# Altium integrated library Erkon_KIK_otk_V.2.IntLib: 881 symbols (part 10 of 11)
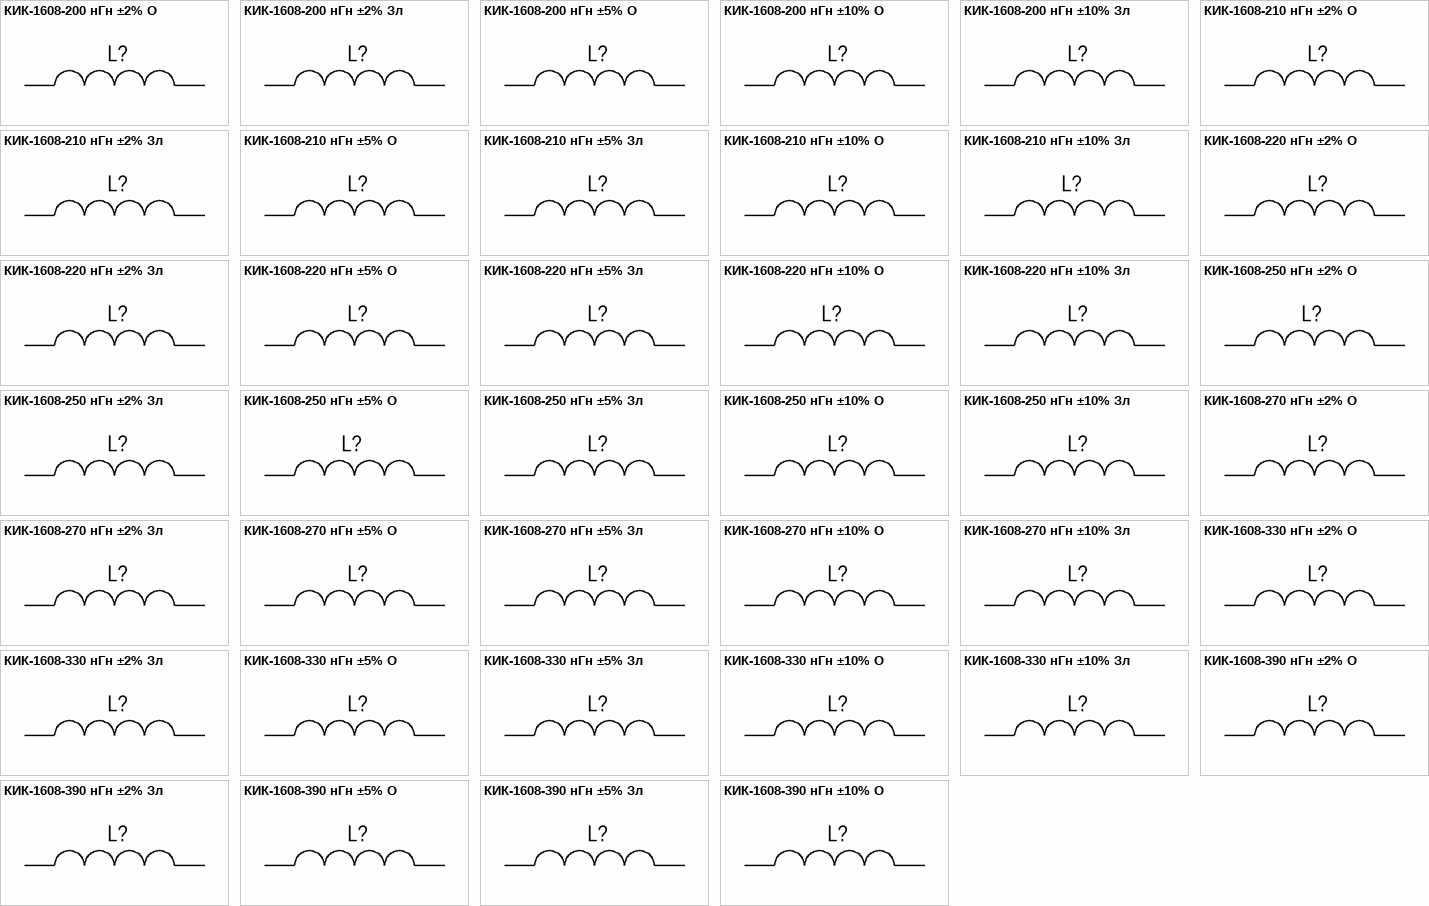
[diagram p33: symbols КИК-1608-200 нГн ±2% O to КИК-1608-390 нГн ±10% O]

## КИК-1608-250 нГн ±5% Зл
designator L?, comment 250 нГн ±5%  (value not drawn)
Катушка индуктивности с керамическим сердечником и золотым покрытием контактных площадок; Номиналиная индуктивность: 250 нГн; Добротность, не менее: 25; Резонансная частота, не менее: 0.822 ГГц; Сопротивление обмотки постоянноми току, не более: 3.55 Ом; Допустимый ток обмотки: 120 мА; Диапазон рабочих температур: от -60 до +125 ℃; Упаковка: Катушка и лента; Типоразмер: 1608 (0603); Технология монтажа: SMT; Изготовитель: АО "НПО "ЭРКОН"
footprint КИК-1608_Зл (Катушка индуктивности с керамическим сердечником  типоразмер 1005(0402))
pins: 1, 2

## КИК-1608-250 нГн ±10% O
designator L?, comment 250 нГн ±10%  (value not drawn)
Катушка индуктивности с керамическим сердечником и  финишным покрытием контактных площадок оловом; Номиналиная индуктивность: 250 нГн; Добротность, не менее: 25; Резонансная частота, не менее: 0.822 ГГц; Сопротивление обмотки постоянноми току, не более: 3.55 Ом; Допустимый ток обмотки: 120 мА; Диапазон рабочих температур: от -60 до +125 ℃; Упаковка: Катушка и лента; Типоразмер: 1608 (0603); Технология монтажа: SMT; Изготовитель: АО "НПО "ЭРКОН"
footprint КИК-1608_О (Катушка индуктивности с керамическим сердечником  типоразмер 1005(0402))
pins: 1, 2

## КИК-1608-250 нГн ±10% Зл
designator L?, comment 250 нГн ±10%  (value not drawn)
Катушка индуктивности с керамическим сердечником и золотым покрытием контактных площадок; Номиналиная индуктивность: 250 нГн; Добротность, не менее: 25; Резонансная частота, не менее: 0.822 ГГц; Сопротивление обмотки постоянноми току, не более: 3.55 Ом; Допустимый ток обмотки: 120 мА; Диапазон рабочих температур: от -60 до +125 ℃; Упаковка: Катушка и лента; Типоразмер: 1608 (0603); Технология монтажа: SMT; Изготовитель: АО "НПО "ЭРКОН"
footprint КИК-1608_Зл (Катушка индуктивности с керамическим сердечником  типоразмер 1005(0402))
pins: 1, 2

## КИК-1608-270 нГн ±2% O
designator L?, comment 270 нГн ±2%  (value not drawn)
Катушка индуктивности с керамическим сердечником и  финишным покрытием контактных площадок оловом; Номиналиная индуктивность: 270 нГн; Добротность, не менее: 25; Резонансная частота, не менее: 0.830 ГГц; Сопротивление обмотки постоянноми току, не более: 2.16 Ом; Допустимый ток обмотки: 170 мА; Диапазон рабочих температур: от -60 до +125 ℃; Упаковка: Катушка и лента; Типоразмер: 1608 (0603); Технология монтажа: SMT; Изготовитель: АО "НПО "ЭРКОН"
footprint КИК-1608_О (Катушка индуктивности с керамическим сердечником  типоразмер 1005(0402))
pins: 1, 2

## КИК-1608-270 нГн ±2% Зл
designator L?, comment 270 нГн ±2%  (value not drawn)
Катушка индуктивности с керамическим сердечником и золотым покрытием контактных площадок; Номиналиная индуктивность: 270 нГн; Добротность, не менее: 25; Резонансная частота, не менее: 0.830 ГГц; Сопротивление обмотки постоянноми току, не более: 2.16 Ом; Допустимый ток обмотки: 170 мА; Диапазон рабочих температур: от -60 до +125 ℃; Упаковка: Катушка и лента; Типоразмер: 1608 (0603); Технология монтажа: SMT; Изготовитель: АО "НПО "ЭРКОН"
footprint КИК-1608_Зл (Катушка индуктивности с керамическим сердечником  типоразмер 1005(0402))
pins: 1, 2

## КИК-1608-270 нГн ±5% O
designator L?, comment 270 нГн ±5%  (value not drawn)
Катушка индуктивности с керамическим сердечником и  финишным покрытием контактных площадок оловом; Номиналиная индуктивность: 270 нГн; Добротность, не менее: 25; Резонансная частота, не менее: 0.830 ГГц; Сопротивление обмотки постоянноми току, не более: 2.16 Ом; Допустимый ток обмотки: 170 мА; Диапазон рабочих температур: от -60 до +125 ℃; Упаковка: Катушка и лента; Типоразмер: 1608 (0603); Технология монтажа: SMT; Изготовитель: АО "НПО "ЭРКОН"
footprint КИК-1608_О (Катушка индуктивности с керамическим сердечником  типоразмер 1005(0402))
pins: 1, 2

## КИК-1608-270 нГн ±5% Зл
designator L?, comment 270 нГн ±5%  (value not drawn)
Катушка индуктивности с керамическим сердечником и золотым покрытием контактных площадок; Номиналиная индуктивность: 270 нГн; Добротность, не менее: 25; Резонансная частота, не менее: 0.830 ГГц; Сопротивление обмотки постоянноми току, не более: 2.16 Ом; Допустимый ток обмотки: 170 мА; Диапазон рабочих температур: от -60 до +125 ℃; Упаковка: Катушка и лента; Типоразмер: 1608 (0603); Технология монтажа: SMT; Изготовитель: АО "НПО "ЭРКОН"
footprint КИК-1608_Зл (Катушка индуктивности с керамическим сердечником  типоразмер 1005(0402))
pins: 1, 2

## КИК-1608-270 нГн ±10% O
designator L?, comment 270 нГн ±10%  (value not drawn)
Катушка индуктивности с керамическим сердечником и  финишным покрытием контактных площадок оловом; Номиналиная индуктивность: 270 нГн; Добротность, не менее: 25; Резонансная частота, не менее: 0.830 ГГц; Сопротивление обмотки постоянноми току, не более: 2.16 Ом; Допустимый ток обмотки: 170 мА; Диапазон рабочих температур: от -60 до +125 ℃; Упаковка: Катушка и лента; Типоразмер: 1608 (0603); Технология монтажа: SMT; Изготовитель: АО "НПО "ЭРКОН"
footprint КИК-1608_О (Катушка индуктивности с керамическим сердечником  типоразмер 1005(0402))
pins: 1, 2

## КИК-1608-270 нГн ±10% Зл
designator L?, comment 270 нГн ±10%  (value not drawn)
Катушка индуктивности с керамическим сердечником и золотым покрытием контактных площадок; Номиналиная индуктивность: 270 нГн; Добротность, не менее: 25; Резонансная частота, не менее: 0.830 ГГц; Сопротивление обмотки постоянноми току, не более: 2.16 Ом; Допустимый ток обмотки: 170 мА; Диапазон рабочих температур: от -60 до +125 ℃; Упаковка: Катушка и лента; Типоразмер: 1608 (0603); Технология монтажа: SMT; Изготовитель: АО "НПО "ЭРКОН"
footprint КИК-1608_Зл (Катушка индуктивности с керамическим сердечником  типоразмер 1005(0402))
pins: 1, 2

## КИК-1608-330 нГн ±2% O
designator L?, comment 330 нГн ±2%  (value not drawn)
Катушка индуктивности с керамическим сердечником и  финишным покрытием контактных площадок оловом; Номиналиная индуктивность: 330 нГн; Добротность, не менее: 25; Резонансная частота, не менее: 0.900 ГГц; Сопротивление обмотки постоянноми току, не более: 3.89 Ом; Допустимый ток обмотки: 100 мА; Диапазон рабочих температур: от -60 до +125 ℃; Упаковка: Катушка и лента; Типоразмер: 1608 (0603); Технология монтажа: SMT; Изготовитель: АО "НПО "ЭРКОН"
footprint КИК-1608_О (Катушка индуктивности с керамическим сердечником  типоразмер 1005(0402))
pins: 1, 2

## КИК-1608-330 нГн ±2% Зл
designator L?, comment 330 нГн ±2%  (value not drawn)
Катушка индуктивности с керамическим сердечником и золотым покрытием контактных площадок; Номиналиная индуктивность: 330 нГн; Добротность, не менее: 25; Резонансная частота, не менее: 0.900 ГГц; Сопротивление обмотки постоянноми току, не более: 3.89 Ом; Допустимый ток обмотки: 100 мА; Диапазон рабочих температур: от -60 до +125 ℃; Упаковка: Катушка и лента; Типоразмер: 1608 (0603); Технология монтажа: SMT; Изготовитель: АО "НПО "ЭРКОН"
footprint КИК-1608_Зл (Катушка индуктивности с керамическим сердечником  типоразмер 1005(0402))
pins: 1, 2

## КИК-1608-330 нГн ±5% O
designator L?, comment 330 нГн ±5%  (value not drawn)
Катушка индуктивности с керамическим сердечником и  финишным покрытием контактных площадок оловом; Номиналиная индуктивность: 330 нГн; Добротность, не менее: 25; Резонансная частота, не менее: 0.900 ГГц; Сопротивление обмотки постоянноми току, не более: 3.89 Ом; Допустимый ток обмотки: 100 мА; Диапазон рабочих температур: от -60 до +125 ℃; Упаковка: Катушка и лента; Типоразмер: 1608 (0603); Технология монтажа: SMT; Изготовитель: АО "НПО "ЭРКОН"
footprint КИК-1608_О (Катушка индуктивности с керамическим сердечником  типоразмер 1005(0402))
pins: 1, 2

## КИК-1608-330 нГн ±5% Зл
designator L?, comment 330 нГн ±5%  (value not drawn)
Катушка индуктивности с керамическим сердечником и золотым покрытием контактных площадок; Номиналиная индуктивность: 330 нГн; Добротность, не менее: 25; Резонансная частота, не менее: 0.900 ГГц; Сопротивление обмотки постоянноми току, не более: 3.89 Ом; Допустимый ток обмотки: 100 мА; Диапазон рабочих температур: от -60 до +125 ℃; Упаковка: Катушка и лента; Типоразмер: 1608 (0603); Технология монтажа: SMT; Изготовитель: АО "НПО "ЭРКОН"
footprint КИК-1608_Зл (Катушка индуктивности с керамическим сердечником  типоразмер 1005(0402))
pins: 1, 2

## КИК-1608-330 нГн ±10% O
designator L?, comment 330 нГн ±10%  (value not drawn)
Катушка индуктивности с керамическим сердечником и  финишным покрытием контактных площадок оловом; Номиналиная индуктивность: 330 нГн; Добротность, не менее: 25; Резонансная частота, не менее: 0.900 ГГц; Сопротивление обмотки постоянноми току, не более: 3.89 Ом; Допустимый ток обмотки: 100 мА; Диапазон рабочих температур: от -60 до +125 ℃; Упаковка: Катушка и лента; Типоразмер: 1608 (0603); Технология монтажа: SMT; Изготовитель: АО "НПО "ЭРКОН"
footprint КИК-1608_О (Катушка индуктивности с керамическим сердечником  типоразмер 1005(0402))
pins: 1, 2

## КИК-1608-330 нГн ±10% Зл
designator L?, comment 330 нГн ±10%  (value not drawn)
Катушка индуктивности с керамическим сердечником и золотым покрытием контактных площадок; Номиналиная индуктивность: 330 нГн; Добротность, не менее: 25; Резонансная частота, не менее: 0.900 ГГц; Сопротивление обмотки постоянноми току, не более: 3.89 Ом; Допустимый ток обмотки: 100 мА; Диапазон рабочих температур: от -60 до +125 ℃; Упаковка: Катушка и лента; Типоразмер: 1608 (0603); Технология монтажа: SMT; Изготовитель: АО "НПО "ЭРКОН"
footprint КИК-1608_Зл (Катушка индуктивности с керамическим сердечником  типоразмер 1005(0402))
pins: 1, 2

## КИК-1608-390 нГн ±2% O
designator L?, comment 390 нГн ±2%  (value not drawn)
Катушка индуктивности с керамическим сердечником и  финишным покрытием контактных площадок оловом; Номиналиная индуктивность: 390 нГн; Добротность, не менее: 25; Резонансная частота, не менее: 0.780 ГГц; Сопротивление обмотки постоянноми току, не более: 4.35 Ом; Допустимый ток обмотки: 100 мА; Диапазон рабочих температур: от -60 до +125 ℃; Упаковка: Катушка и лента; Типоразмер: 1608 (0603); Технология монтажа: SMT; Изготовитель: АО "НПО "ЭРКОН"
footprint КИК-1608_О (Катушка индуктивности с керамическим сердечником  типоразмер 1005(0402))
pins: 1, 2

## КИК-1608-390 нГн ±2% Зл
designator L?, comment 390 нГн ±2%  (value not drawn)
Катушка индуктивности с керамическим сердечником и золотым покрытием контактных площадок; Номиналиная индуктивность: 390 нГн; Добротность, не менее: 25; Резонансная частота, не менее: 0.780 ГГц; Сопротивление обмотки постоянноми току, не более: 4.35 Ом; Допустимый ток обмотки: 100 мА; Диапазон рабочих температур: от -60 до +125 ℃; Упаковка: Катушка и лента; Типоразмер: 1608 (0603); Технология монтажа: SMT; Изготовитель: АО "НПО "ЭРКОН"
footprint КИК-1608_Зл (Катушка индуктивности с керамическим сердечником  типоразмер 1005(0402))
pins: 1, 2

## КИК-1608-390 нГн ±5% O
designator L?, comment 390 нГн ±5%  (value not drawn)
Катушка индуктивности с керамическим сердечником и  финишным покрытием контактных площадок оловом; Номиналиная индуктивность: 390 нГн; Добротность, не менее: 25; Резонансная частота, не менее: 0.780 ГГц; Сопротивление обмотки постоянноми току, не более: 4.35 Ом; Допустимый ток обмотки: 100 мА; Диапазон рабочих температур: от -60 до +125 ℃; Упаковка: Катушка и лента; Типоразмер: 1608 (0603); Технология монтажа: SMT; Изготовитель: АО "НПО "ЭРКОН"
footprint КИК-1608_О (Катушка индуктивности с керамическим сердечником  типоразмер 1005(0402))
pins: 1, 2

## КИК-1608-390 нГн ±5% Зл
designator L?, comment 390 нГн ±5%  (value not drawn)
Катушка индуктивности с керамическим сердечником и золотым покрытием контактных площадок; Номиналиная индуктивность: 390 нГн; Добротность, не менее: 25; Резонансная частота, не менее: 0.780 ГГц; Сопротивление обмотки постоянноми току, не более: 4.35 Ом; Допустимый ток обмотки: 100 мА; Диапазон рабочих температур: от -60 до +125 ℃; Упаковка: Катушка и лента; Типоразмер: 1608 (0603); Технология монтажа: SMT; Изготовитель: АО "НПО "ЭРКОН"
footprint КИК-1608_Зл (Катушка индуктивности с керамическим сердечником  типоразмер 1005(0402))
pins: 1, 2

## КИК-1608-390 нГн ±10% O
designator L?, comment 390 нГн ±10%  (value not drawn)
Катушка индуктивности с керамическим сердечником и  финишным покрытием контактных площадок оловом; Номиналиная индуктивность: 390 нГн; Добротность, не менее: 25; Резонансная частота, не менее: 0.780 ГГц; Сопротивление обмотки постоянноми току, не более: 4.35 Ом; Допустимый ток обмотки: 100 мА; Диапазон рабочих температур: от -60 до +125 ℃; Упаковка: Катушка и лента; Типоразмер: 1608 (0603); Технология монтажа: SMT; Изготовитель: АО "НПО "ЭРКОН"
footprint КИК-1608_О (Катушка индуктивности с керамическим сердечником  типоразмер 1005(0402))
pins: 1, 2

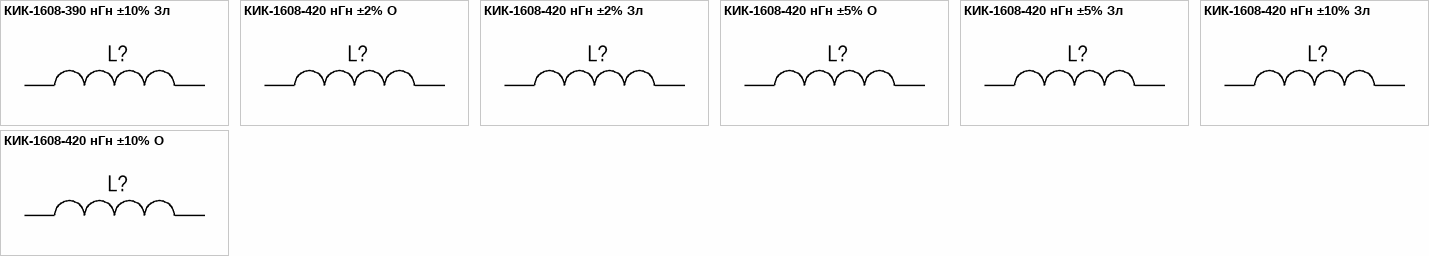
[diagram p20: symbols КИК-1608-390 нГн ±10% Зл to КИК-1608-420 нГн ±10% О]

## КИК-1608-390 нГн ±10% Зл
designator L?, comment 390 нГн ±10%  (value not drawn)
Катушка индуктивности с керамическим сердечником и золотым покрытием контактных площадок; Номиналиная индуктивность: 390 нГн; Добротность, не менее: 25; Резонансная частота, не менее: 0.780 ГГц; Сопротивление обмотки постоянноми току, не более: 4.35 Ом; Допустимый ток обмотки: 100 мА; Диапазон рабочих температур: от -60 до +125 ℃; Упаковка: Катушка и лента; Типоразмер: 1608 (0603); Технология монтажа: SMT; Изготовитель: АО "НПО "ЭРКОН"
footprint КИК-1608_Зл (Катушка индуктивности с керамическим сердечником  типоразмер 1005(0402))
pins: 1, 2

## КИК-1608-420 нГн ±2% O
designator L?, comment 420 нГн ±2%  (value not drawn)
Катушка индуктивности с керамическим сердечником и  финишным покрытием контактных площадок оловом; Номиналиная индуктивность: 420 нГн; Добротность, не менее: 20; Резонансная частота, не менее: 0.680 ГГц; Сопротивление обмотки постоянноми току, не более: 4.45 Ом; Допустимый ток обмотки: 100 мА; Диапазон рабочих температур: от -60 до +125 ℃; Упаковка: Катушка и лента; Типоразмер: 1608 (0603); Технология монтажа: SMT; Изготовитель: АО "НПО "ЭРКОН"
footprint КИК-1608_О (Катушка индуктивности с керамическим сердечником  типоразмер 1005(0402))
pins: 1, 2

## КИК-1608-420 нГн ±2% Зл
designator L?, comment 420 нГн ±2%  (value not drawn)
Катушка индуктивности с керамическим сердечником и золотым покрытием контактных площадок; Номиналиная индуктивность: 420 нГн; Добротность, не менее: 20; Резонансная частота, не менее: 0.680 ГГц; Сопротивление обмотки постоянноми току, не более: 4.45 Ом; Допустимый ток обмотки: 100 мА; Диапазон рабочих температур: от -60 до +125 ℃; Упаковка: Катушка и лента; Типоразмер: 1608 (0603); Технология монтажа: SMT; Изготовитель: АО "НПО "ЭРКОН"
footprint КИК-1608_Зл (Катушка индуктивности с керамическим сердечником  типоразмер 1005(0402))
pins: 1, 2

## КИК-1608-420 нГн ±5% O
designator L?, comment 420 нГн ±5%  (value not drawn)
Катушка индуктивности с керамическим сердечником и  финишным покрытием контактных площадок оловом; Номиналиная индуктивность: 420 нГн; Добротность, не менее: 20; Резонансная частота, не менее: 0.680 ГГц; Сопротивление обмотки постоянноми току, не более: 4.45 Ом; Допустимый ток обмотки: 100 мА; Диапазон рабочих температур: от -60 до +125 ℃; Упаковка: Катушка и лента; Типоразмер: 1608 (0603); Технология монтажа: SMT; Изготовитель: АО "НПО "ЭРКОН"
footprint КИК-1608_О (Катушка индуктивности с керамическим сердечником  типоразмер 1005(0402))
pins: 1, 2

## КИК-1608-420 нГн ±5% Зл
designator L?, comment 420 нГн ±5%  (value not drawn)
Катушка индуктивности с керамическим сердечником и золотым покрытием контактных площадок; Номиналиная индуктивность: 420 нГн; Добротность, не менее: 20; Резонансная частота, не менее: 0.680 ГГц; Сопротивление обмотки постоянноми току, не более: 4.45 Ом; Допустимый ток обмотки: 100 мА; Диапазон рабочих температур: от -60 до +125 ℃; Упаковка: Катушка и лента; Типоразмер: 1608 (0603); Технология монтажа: SMT; Изготовитель: АО "НПО "ЭРКОН"
footprint КИК-1608_Зл (Катушка индуктивности с керамическим сердечником  типоразмер 1005(0402))
pins: 1, 2

## КИК-1608-420 нГн ±10% Зл
designator L?, comment 420 нГн ±10%  (value not drawn)
Катушка индуктивности с керамическим сердечником и золотым покрытием контактных площадок; Номиналиная индуктивность: 420 нГн; Добротность, не менее: 20; Резонансная частота, не менее: 0.680 ГГц; Сопротивление обмотки постоянноми току, не более: 4.45 Ом; Допустимый ток обмотки: 100 мА; Диапазон рабочих температур: от -60 до +125 ℃; Упаковка: Катушка и лента; Типоразмер: 1608 (0603); Технология монтажа: SMT; Изготовитель: АО "НПО "ЭРКОН"
footprint КИК-1608_Зл (Катушка индуктивности с керамическим сердечником  типоразмер 1005(0402))
pins: 1, 2

## КИК-1608-420 нГн ±10% О
designator L?, comment 420 нГн ±10%  (value not drawn)
Катушка индуктивности с керамическим сердечником и  финишным покрытием контактных площадок оловом; Номиналиная индуктивность: 420 нГн; Добротность, не менее: 20; Резонансная частота, не менее: 0.680 ГГц; Сопротивление обмотки постоянноми току, не более: 4.45 Ом; Допустимый ток обмотки: 100 мА; Диапазон рабочих температур: от -60 до +125 ℃; Упаковка: Катушка и лента; Типоразмер: 1608 (0603); Технология монтажа: SMT; Изготовитель: АО "НПО "ЭРКОН"
footprint КИК-1608_О (Катушка индуктивности с керамическим сердечником  типоразмер 1005(0402))
pins: 1, 2


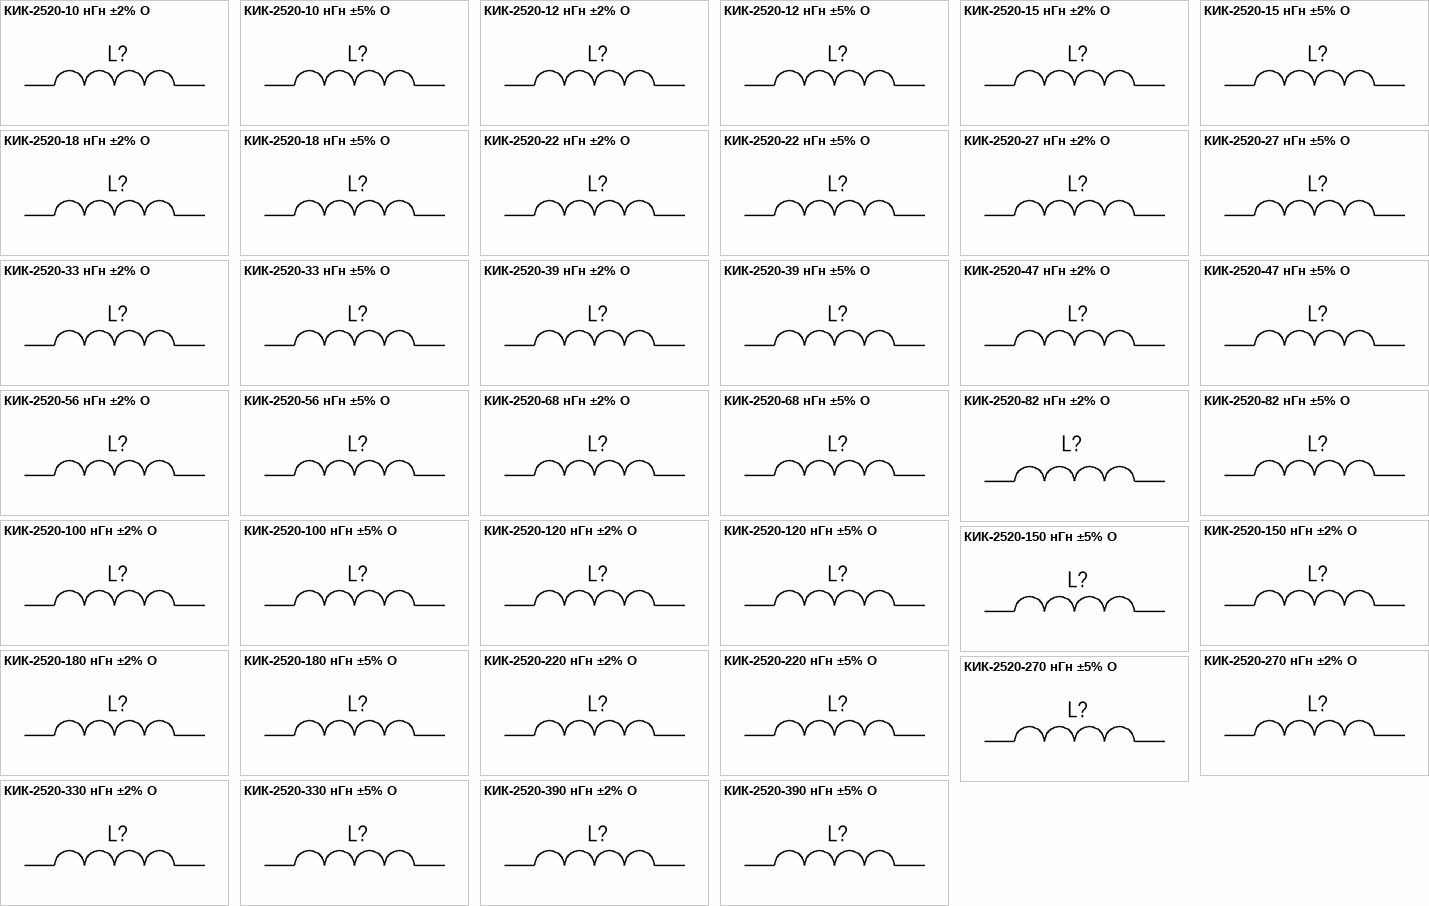
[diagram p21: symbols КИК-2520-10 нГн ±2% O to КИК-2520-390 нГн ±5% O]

## КИК-2520-10 нГн ±2% O
designator L?, comment 10 нГн ±2%  (value not drawn)
Катушка индуктивности с керамическим сердечником и  финишным покрытием контактных площадок оловом; Номиналиная индуктивность: 10 нГн; Добротность, не менее: 50; Резонансная частота, не менее: 4.10 ГГц; Сопротивление обмотки постоянноми току, не более: 0.08 Ом; Допустимый ток обмотки: 1000 мА; Диапазон рабочих температур: от -60 до +125 ℃; Упаковка: Катушка и лента; Типоразмер: 2520 (1008); Технология монтажа: SMT; Изготовитель: АО "НПО "ЭРКОН"
footprint КИК-2520-О (Катушка индуктивности с керамическим сердечником типоразмер 2520(1008))
pins: 1, 2

## КИК-2520-10 нГн ±5% O
designator L?, comment 10 нГн ±5%  (value not drawn)
Катушка индуктивности с керамическим сердечником и  финишным покрытием контактных площадок оловом; Номиналиная индуктивность: 10 нГн; Добротность, не менее: 50; Резонансная частота, не менее: 4.10 ГГц; Сопротивление обмотки постоянноми току, не более: 0.08 Ом; Допустимый ток обмотки: 1000 мА; Диапазон рабочих температур: от -60 до +125 ℃; Упаковка: Катушка и лента; Типоразмер: 2520 (1008); Технология монтажа: SMT; Изготовитель: АО "НПО "ЭРКОН"
footprint КИК-2520-О (Катушка индуктивности с керамическим сердечником типоразмер 2520(1008))
pins: 1, 2

## КИК-2520-12 нГн ±2% O
designator L?, comment 12 нГн ±2%  (value not drawn)
Катушка индуктивности с керамическим сердечником и  финишным покрытием контактных площадок оловом; Номиналиная индуктивность: 12 нГн; Добротность, не менее: 50; Резонансная частота, не менее: 3.30 ГГц; Сопротивление обмотки постоянноми току, не более: 0.09 Ом; Допустимый ток обмотки: 1000 мА; Диапазон рабочих температур: от -60 до +125 ℃; Упаковка: Катушка и лента; Типоразмер: 2520 (1008); Технология монтажа: SMT; Изготовитель: АО "НПО "ЭРКОН"
footprint КИК-2520-О (Катушка индуктивности с керамическим сердечником типоразмер 2520(1008))
pins: 1, 2

## КИК-2520-12 нГн ±5% O
designator L?, comment 12 нГн ±5%  (value not drawn)
Катушка индуктивности с керамическим сердечником и  финишным покрытием контактных площадок оловом; Номиналиная индуктивность: 12 нГн; Добротность, не менее: 50; Резонансная частота, не менее: 3.30 ГГц; Сопротивление обмотки постоянноми току, не более: 0.09 Ом; Допустимый ток обмотки: 1000 мА; Диапазон рабочих температур: от -60 до +125 ℃; Упаковка: Катушка и лента; Типоразмер: 2520 (1008); Технология монтажа: SMT; Изготовитель: АО "НПО "ЭРКОН"
footprint КИК-2520-О (Катушка индуктивности с керамическим сердечником типоразмер 2520(1008))
pins: 1, 2

## КИК-2520-15 нГн ±2% O
designator L?, comment 15 нГн ±2%  (value not drawn)
Катушка индуктивности с керамическим сердечником и  финишным покрытием контактных площадок оловом; Номиналиная индуктивность: 15 нГн; Добротность, не менее: 50; Резонансная частота, не менее: 2.50 ГГц; Сопротивление обмотки постоянноми току, не более: 0.10 Ом; Допустимый ток обмотки: 1000 мА; Диапазон рабочих температур: от -60 до +125 ℃; Упаковка: Катушка и лента; Типоразмер: 2520 (1008); Технология монтажа: SMT; Изготовитель: АО "НПО "ЭРКОН"
footprint КИК-2520-О (Катушка индуктивности с керамическим сердечником типоразмер 2520(1008))
pins: 1, 2

## КИК-2520-15 нГн ±5% O
designator L?, comment 15 нГн ±5%  (value not drawn)
Катушка индуктивности с керамическим сердечником и  финишным покрытием контактных площадок оловом; Номиналиная индуктивность: 15 нГн; Добротность, не менее: 50; Резонансная частота, не менее: 2.50 ГГц; Сопротивление обмотки постоянноми току, не более: 0.10 Ом; Допустимый ток обмотки: 1000 мА; Диапазон рабочих температур: от -60 до +125 ℃; Упаковка: Катушка и лента; Типоразмер: 2520 (1008); Технология монтажа: SMT; Изготовитель: АО "НПО "ЭРКОН"
footprint КИК-2520-О (Катушка индуктивности с керамическим сердечником типоразмер 2520(1008))
pins: 1, 2

## КИК-2520-18 нГн ±2% O
designator L?, comment 18 нГн ±2%  (value not drawn)
Катушка индуктивности с керамическим сердечником и  финишным покрытием контактных площадок оловом; Номиналиная индуктивность: 18 нГн; Добротность, не менее: 50; Резонансная частота, не менее: 2.50 ГГц; Сопротивление обмотки постоянноми току, не более: 0.11 Ом; Допустимый ток обмотки: 1000 мА; Диапазон рабочих температур: от -60 до +125 ℃; Упаковка: Катушка и лента; Типоразмер: 2520 (1008); Технология монтажа: SMT; Изготовитель: АО "НПО "ЭРКОН"
footprint КИК-2520-О (Катушка индуктивности с керамическим сердечником типоразмер 2520(1008))
pins: 1, 2

## КИК-2520-18 нГн ±5% O
designator L?, comment 18 нГн ±5%  (value not drawn)
Катушка индуктивности с керамическим сердечником и  финишным покрытием контактных площадок оловом; Номиналиная индуктивность: 18 нГн; Добротность, не менее: 50; Резонансная частота, не менее: 2.50 ГГц; Сопротивление обмотки постоянноми току, не более: 0.11 Ом; Допустимый ток обмотки: 1000 мА; Диапазон рабочих температур: от -60 до +125 ℃; Упаковка: Катушка и лента; Типоразмер: 2520 (1008); Технология монтажа: SMT; Изготовитель: АО "НПО "ЭРКОН"
footprint КИК-2520-О (Катушка индуктивности с керамическим сердечником типоразмер 2520(1008))
pins: 1, 2

## КИК-2520-22 нГн ±2% O
designator L?, comment 22 нГн ±2%  (value not drawn)
Катушка индуктивности с керамическим сердечником и  финишным покрытием контактных площадок оловом; Номиналиная индуктивность: 22 нГн; Добротность, не менее: 55; Резонансная частота, не менее: 2.40 ГГц; Сопротивление обмотки постоянноми току, не более: 0.12 Ом; Допустимый ток обмотки: 1000 мА; Диапазон рабочих температур: от -60 до +125 ℃; Упаковка: Катушка и лента; Типоразмер: 2520 (1008); Технология монтажа: SMT; Изготовитель: АО "НПО "ЭРКОН"
footprint КИК-2520-О (Катушка индуктивности с керамическим сердечником типоразмер 2520(1008))
pins: 1, 2

## КИК-2520-22 нГн ±5% O
designator L?, comment 22 нГн ±5%  (value not drawn)
Катушка индуктивности с керамическим сердечником и  финишным покрытием контактных площадок оловом; Номиналиная индуктивность: 22 нГн; Добротность, не менее: 55; Резонансная частота, не менее: 2.40 ГГц; Сопротивление обмотки постоянноми току, не более: 0.12 Ом; Допустимый ток обмотки: 1000 мА; Диапазон рабочих температур: от -60 до +125 ℃; Упаковка: Катушка и лента; Типоразмер: 2520 (1008); Технология монтажа: SMT; Изготовитель: АО "НПО "ЭРКОН"
footprint КИК-2520-О (Катушка индуктивности с керамическим сердечником типоразмер 2520(1008))
pins: 1, 2

## КИК-2520-27 нГн ±2% O
designator L?, comment 27 нГн ±2%  (value not drawn)
Катушка индуктивности с керамическим сердечником и  финишным покрытием контактных площадок оловом; Номиналиная индуктивность: 27 нГн; Добротность, не менее: 55; Резонансная частота, не менее: 1.60 ГГц; Сопротивление обмотки постоянноми току, не более: 0.13 Ом; Допустимый ток обмотки: 1000 мА; Диапазон рабочих температур: от -60 до +125 ℃; Упаковка: Катушка и лента; Типоразмер: 2520 (1008); Технология монтажа: SMT; Изготовитель: АО "НПО "ЭРКОН"
footprint КИК-2520-О (Катушка индуктивности с керамическим сердечником типоразмер 2520(1008))
pins: 1, 2

## КИК-2520-27 нГн ±5% O
designator L?, comment 27 нГн ±5%  (value not drawn)
Катушка индуктивности с керамическим сердечником и  финишным покрытием контактных площадок оловом; Номиналиная индуктивность: 27 нГн; Добротность, не менее: 55; Резонансная частота, не менее: 1.60 ГГц; Сопротивление обмотки постоянноми току, не более: 0.13 Ом; Допустимый ток обмотки: 1000 мА; Диапазон рабочих температур: от -60 до +125 ℃; Упаковка: Катушка и лента; Типоразмер: 2520 (1008); Технология монтажа: SMT; Изготовитель: АО "НПО "ЭРКОН"
footprint КИК-2520-О (Катушка индуктивности с керамическим сердечником типоразмер 2520(1008))
pins: 1, 2

## КИК-2520-33 нГн ±2% O
designator L?, comment 33 нГн ±2%  (value not drawn)
Катушка индуктивности с керамическим сердечником и  финишным покрытием контактных площадок оловом; Номиналиная индуктивность: 33 нГн; Добротность, не менее: 60; Резонансная частота, не менее: 1.60 ГГц; Сопротивление обмотки постоянноми току, не более: 0.14 Ом; Допустимый ток обмотки: 1000 мА; Диапазон рабочих температур: от -60 до +125 ℃; Упаковка: Катушка и лента; Типоразмер: 2520 (1008); Технология монтажа: SMT; Изготовитель: АО "НПО "ЭРКОН"
footprint КИК-2520-О (Катушка индуктивности с керамическим сердечником типоразмер 2520(1008))
pins: 1, 2

## КИК-2520-33 нГн ±5% O
designator L?, comment 33 нГн ±5%  (value not drawn)
Катушка индуктивности с керамическим сердечником и  финишным покрытием контактных площадок оловом; Номиналиная индуктивность: 33 нГн; Добротность, не менее: 60; Резонансная частота, не менее: 1.60 ГГц; Сопротивление обмотки постоянноми току, не более: 0.14 Ом; Допустимый ток обмотки: 1000 мА; Диапазон рабочих температур: от -60 до +125 ℃; Упаковка: Катушка и лента; Типоразмер: 2520 (1008); Технология монтажа: SMT; Изготовитель: АО "НПО "ЭРКОН"
footprint КИК-2520-О (Катушка индуктивности с керамическим сердечником типоразмер 2520(1008))
pins: 1, 2

## КИК-2520-39 нГн ±2% O
designator L?, comment 39 нГн ±2%  (value not drawn)
Катушка индуктивности с керамическим сердечником и  финишным покрытием контактных площадок оловом; Номиналиная индуктивность: 33 нГн; Добротность, не менее: 60; Резонансная частота, не менее: 1.50 ГГц; Сопротивление обмотки постоянноми току, не более: 0.15 Ом; Допустимый ток обмотки: 1000 мА; Диапазон рабочих температур: от -60 до +125 ℃; Упаковка: Катушка и лента; Типоразмер: 2520 (1008); Технология монтажа: SMT; Изготовитель: АО "НПО "ЭРКОН"
footprint КИК-2520-О (Катушка индуктивности с керамическим сердечником типоразмер 2520(1008))
pins: 1, 2

## КИК-2520-39 нГн ±5% O
designator L?, comment 39 нГн ±5%  (value not drawn)
Катушка индуктивности с керамическим сердечником и  финишным покрытием контактных площадок оловом; Номиналиная индуктивность: 33 нГн; Добротность, не менее: 60; Резонансная частота, не менее: 1.50 ГГц; Сопротивление обмотки постоянноми току, не более: 0.15 Ом; Допустимый ток обмотки: 1000 мА; Диапазон рабочих температур: от -60 до +125 ℃; Упаковка: Катушка и лента; Типоразмер: 2520 (1008); Технология монтажа: SMT; Изготовитель: АО "НПО "ЭРКОН"
footprint КИК-2520-О (Катушка индуктивности с керамическим сердечником типоразмер 2520(1008))
pins: 1, 2

## КИК-2520-47 нГн ±2% O
designator L?, comment 47 нГн ±2%  (value not drawn)
Катушка индуктивности с керамическим сердечником и  финишным покрытием контактных площадок оловом; Номиналиная индуктивность: 47 нГн; Добротность, не менее: 65; Резонансная частота, не менее: 1.50 ГГц; Сопротивление обмотки постоянноми току, не более: 0.16 Ом; Допустимый ток обмотки: 1000 мА; Диапазон рабочих температур: от -60 до +125 ℃; Упаковка: Катушка и лента; Типоразмер: 2520 (1008); Технология монтажа: SMT; Изготовитель: АО "НПО "ЭРКОН"
footprint КИК-2520-О (Катушка индуктивности с керамическим сердечником типоразмер 2520(1008))
pins: 1, 2

## КИК-2520-47 нГн ±5% O
designator L?, comment 47 нГн ±5%  (value not drawn)
Катушка индуктивности с керамическим сердечником и  финишным покрытием контактных площадок оловом; Номиналиная индуктивность: 47 нГн; Добротность, не менее: 65; Резонансная частота, не менее: 1.50 ГГц; Сопротивление обмотки постоянноми току, не более: 0.16 Ом; Допустимый ток обмотки: 1000 мА; Диапазон рабочих температур: от -60 до +125 ℃; Упаковка: Катушка и лента; Типоразмер: 2520 (1008); Технология монтажа: SMT; Изготовитель: АО "НПО "ЭРКОН"
footprint КИК-2520-О (Катушка индуктивности с керамическим сердечником типоразмер 2520(1008))
pins: 1, 2

## КИК-2520-56 нГн ±2% O
designator L?, comment 56 нГн ±2%  (value not drawn)
Катушка индуктивности с керамическим сердечником и  финишным покрытием контактных площадок оловом; Номиналиная индуктивность: 56 нГн; Добротность, не менее: 65; Резонансная частота, не менее: 1.30 ГГц; Сопротивление обмотки постоянноми току, не более: 0.18 Ом; Допустимый ток обмотки: 1000 мА; Диапазон рабочих температур: от -60 до +125 ℃; Упаковка: Катушка и лента; Типоразмер: 2520 (1008); Технология монтажа: SMT; Изготовитель: АО "НПО "ЭРКОН"
footprint КИК-2520-О (Катушка индуктивности с керамическим сердечником типоразмер 2520(1008))
pins: 1, 2

## КИК-2520-56 нГн ±5% O
designator L?, comment 56 нГн ±5%  (value not drawn)
Катушка индуктивности с керамическим сердечником и  финишным покрытием контактных площадок оловом; Номиналиная индуктивность: 56 нГн; Добротность, не менее: 65; Резонансная частота, не менее: 1.30 ГГц; Сопротивление обмотки постоянноми току, не более: 0.18 Ом; Допустимый ток обмотки: 1000 мА; Диапазон рабочих температур: от -60 до +125 ℃; Упаковка: Катушка и лента; Типоразмер: 2520 (1008); Технология монтажа: SMT; Изготовитель: АО "НПО "ЭРКОН"
footprint КИК-2520-О (Катушка индуктивности с керамическим сердечником типоразмер 2520(1008))
pins: 1, 2

## КИК-2520-68 нГн ±2% O
designator L?, comment 68 нГн ±2%  (value not drawn)
Катушка индуктивности с керамическим сердечником и  финишным покрытием контактных площадок оловом; Номиналиная индуктивность: 68 нГн; Добротность, не менее: 65; Резонансная частота, не менее: 1.30 ГГц; Сопротивление обмотки постоянноми току, не более: 0.20 Ом; Допустимый ток обмотки: 1000 мА; Диапазон рабочих температур: от -60 до +125 ℃; Упаковка: Катушка и лента; Типоразмер: 2520 (1008); Технология монтажа: SMT; Изготовитель: АО "НПО "ЭРКОН"
footprint КИК-2520-О (Катушка индуктивности с керамическим сердечником типоразмер 2520(1008))
pins: 1, 2

## КИК-2520-68 нГн ±5% O
designator L?, comment 68 нГн ±5%  (value not drawn)
Катушка индуктивности с керамическим сердечником и  финишным покрытием контактных площадок оловом; Номиналиная индуктивность: 68 нГн; Добротность, не менее: 65; Резонансная частота, не менее: 1.30 ГГц; Сопротивление обмотки постоянноми току, не более: 0.20 Ом; Допустимый ток обмотки: 1000 мА; Диапазон рабочих температур: от -60 до +125 ℃; Упаковка: Катушка и лента; Типоразмер: 2520 (1008); Технология монтажа: SMT; Изготовитель: АО "НПО "ЭРКОН"
footprint КИК-2520-О (Катушка индуктивности с керамическим сердечником типоразмер 2520(1008))
pins: 1, 2

## КИК-2520-82 нГн ±2% O
designator L?, comment 82 нГн ±2%  (value not drawn)
Катушка индуктивности с керамическим сердечником и  финишным покрытием контактных площадок оловом; Номиналиная индуктивность: 82 нГн; Добротность, не менее: 60; Резонансная частота, не менее: 1.00 ГГц; Сопротивление обмотки постоянноми току, не более: 0.22 Ом; Допустимый ток обмотки: 1000 мА; Диапазон рабочих температур: от -60 до +125 ℃; Упаковка: Катушка и лента; Типоразмер: 2520 (1008); Технология монтажа: SMT; Изготовитель: АО "НПО "ЭРКОН"
footprint КИК-2520-О (Катушка индуктивности с керамическим сердечником типоразмер 2520(1008))
pins: 1, 2

## КИК-2520-82 нГн ±5% O
designator L?, comment 82 нГн ±5%  (value not drawn)
Катушка индуктивности с керамическим сердечником и  финишным покрытием контактных площадок оловом; Номиналиная индуктивность: 82 нГн; Добротность, не менее: 60; Резонансная частота, не менее: 1.00 ГГц; Сопротивление обмотки постоянноми току, не более: 0.22 Ом; Допустимый ток обмотки: 1000 мА; Диапазон рабочих температур: от -60 до +125 ℃; Упаковка: Катушка и лента; Типоразмер: 2520 (1008); Технология монтажа: SMT; Изготовитель: АО "НПО "ЭРКОН"
footprint КИК-2520-О (Катушка индуктивности с керамическим сердечником типоразмер 2520(1008))
pins: 1, 2

## КИК-2520-100 нГн ±2% O
designator L?, comment 100 нГн ±2%  (value not drawn)
Катушка индуктивности с керамическим сердечником и  финишным покрытием контактных площадок оловом; Номиналиная индуктивность: 100 нГн; Добротность, не менее: 60; Резонансная частота, не менее: 1.00 ГГц; Сопротивление обмотки постоянноми току, не более: 0.56 Ом; Допустимый ток обмотки: 650 мА; Диапазон рабочих температур: от -60 до +125 ℃; Упаковка: Катушка и лента; Типоразмер: 2520 (1008); Технология монтажа: SMT; Изготовитель: АО "НПО "ЭРКОН"
footprint КИК-2520-О (Катушка индуктивности с керамическим сердечником типоразмер 2520(1008))
pins: 1, 2

## КИК-2520-100 нГн ±5% O
designator L?, comment 100 нГн ±5%  (value not drawn)
Катушка индуктивности с керамическим сердечником и  финишным покрытием контактных площадок оловом; Номиналиная индуктивность: 100 нГн; Добротность, не менее: 60; Резонансная частота, не менее: 1.00 ГГц; Сопротивление обмотки постоянноми току, не более: 0.56 Ом; Допустимый ток обмотки: 650 мА; Диапазон рабочих температур: от -60 до +125 ℃; Упаковка: Катушка и лента; Типоразмер: 2520 (1008); Технология монтажа: SMT; Изготовитель: АО "НПО "ЭРКОН"
footprint КИК-2520-О (Катушка индуктивности с керамическим сердечником типоразмер 2520(1008))
pins: 1, 2

## КИК-2520-120 нГн ±2% O
designator L?, comment 120 нГн ±2%  (value not drawn)
Катушка индуктивности с керамическим сердечником и  финишным покрытием контактных площадок оловом; Номиналиная индуктивность: 120 нГн; Добротность, не менее: 60; Резонансная частота, не менее: 0.950 ГГц; Сопротивление обмотки постоянноми току, не более: 0.63 Ом; Допустимый ток обмотки: 650 мА; Диапазон рабочих температур: от -60 до +125 ℃; Упаковка: Катушка и лента; Типоразмер: 2520 (1008); Технология монтажа: SMT; Изготовитель: АО "НПО "ЭРКОН"
footprint КИК-2520-О (Катушка индуктивности с керамическим сердечником типоразмер 2520(1008))
pins: 1, 2

## КИК-2520-120 нГн ±5% O
designator L?, comment 120 нГн ±5%  (value not drawn)
Катушка индуктивности с керамическим сердечником и  финишным покрытием контактных площадок оловом; Номиналиная индуктивность: 120 нГн; Добротность, не менее: 60; Резонансная частота, не менее: 0.950 ГГц; Сопротивление обмотки постоянноми току, не более: 0.63 Ом; Допустимый ток обмотки: 650 мА; Диапазон рабочих температур: от -60 до +125 ℃; Упаковка: Катушка и лента; Типоразмер: 2520 (1008); Технология монтажа: SMT; Изготовитель: АО "НПО "ЭРКОН"
footprint КИК-2520-О (Катушка индуктивности с керамическим сердечником типоразмер 2520(1008))
pins: 1, 2

## КИК-2520-150 нГн ±2% O
designator L?, comment 150 нГн ±10%  (value not drawn)
Катушка индуктивности с керамическим сердечником и  финишным покрытием контактных площадок оловом; Номиналиная индуктивность: 150 нГн; Допускаемое отклонение индуктивности: ±2%; Добротность, не менее: 45; Резонансная частота, не менее: 0.850 ГГц; Сопротивление обмотки постоянноми току, не более: 0.70 Ом; Допустимый ток обмотки: 580 мА; Диапазон рабочих температур: от -60 до +125 ℃; Упаковка: Катушка и лента; Типоразмер: 2520 (1008); Технология монтажа: SMT; Изготовитель: АО "НПО "ЭРКОН"
footprint КИК-2520-О (Катушка индуктивности с керамическим сердечником типоразмер 2520(1008))
pins: 1, 2

## КИК-2520-150 нГн ±5% O
designator L?, comment 150 нГн ±5%  (value not drawn)
Катушка индуктивности с керамическим сердечником и  финишным покрытием контактных площадок оловом; Номиналиная индуктивность: 150 нГн; Добротность, не менее: 45; Резонансная частота, не менее: 0.850 ГГц; Сопротивление обмотки постоянноми току, не более: 0.70 Ом; Допустимый ток обмотки: 580 мА; Диапазон рабочих температур: от -60 до +125 ℃; Упаковка: Катушка и лента; Типоразмер: 2520 (1008); Технология монтажа: SMT; Изготовитель: АО "НПО "ЭРКОН"
footprint КИК-2520-О (Катушка индуктивности с керамическим сердечником типоразмер 2520(1008))
pins: 1, 2

## КИК-2520-180 нГн ±2% O
designator L?, comment 180 нГн ±2%  (value not drawn)
Катушка индуктивности с керамическим сердечником и  финишным покрытием контактных площадок оловом; Номиналиная индуктивность: 180 нГн; Добротность, не менее: 45; Резонансная частота, не менее: 0.750 ГГц; Сопротивление обмотки постоянноми току, не более: 0.77 Ом; Допустимый ток обмотки: 620 мА; Диапазон рабочих температур: от -60 до +125 ℃; Упаковка: Катушка и лента; Типоразмер: 2520 (1008); Технология монтажа: SMT; Изготовитель: АО "НПО "ЭРКОН"
footprint КИК-2520-О (Катушка индуктивности с керамическим сердечником типоразмер 2520(1008))
pins: 1, 2

## КИК-2520-180 нГн ±5% O
designator L?, comment 180 нГн ±5%  (value not drawn)
Катушка индуктивности с керамическим сердечником и  финишным покрытием контактных площадок оловом; Номиналиная индуктивность: 180 нГн; Добротность, не менее: 45; Резонансная частота, не менее: 0.750 ГГц; Сопротивление обмотки постоянноми току, не более: 0.77 Ом; Допустимый ток обмотки: 620 мА; Диапазон рабочих температур: от -60 до +125 ℃; Упаковка: Катушка и лента; Типоразмер: 2520 (1008); Технология монтажа: SMT; Изготовитель: АО "НПО "ЭРКОН"
footprint КИК-2520-О (Катушка индуктивности с керамическим сердечником типоразмер 2520(1008))
pins: 1, 2

## КИК-2520-220 нГн ±2% O
designator L?, comment 220 нГн ±2%  (value not drawn)
Катушка индуктивности с керамическим сердечником и  финишным покрытием контактных площадок оловом; Номиналиная индуктивность: 220 нГн; Добротность, не менее: 45; Резонансная частота, не менее: 0.700 ГГц; Сопротивление обмотки постоянноми току, не более: 0.84 Ом; Допустимый ток обмотки: 500 мА; Диапазон рабочих температур: от -60 до +125 ℃; Упаковка: Катушка и лента; Типоразмер: 2520 (1008); Технология монтажа: SMT; Изготовитель: АО "НПО "ЭРКОН"
footprint КИК-2520-О (Катушка индуктивности с керамическим сердечником типоразмер 2520(1008))
pins: 1, 2

## КИК-2520-220 нГн ±5% O
designator L?, comment 220 нГн ±5%  (value not drawn)
Катушка индуктивности с керамическим сердечником и  финишным покрытием контактных площадок оловом; Номиналиная индуктивность: 220 нГн; Добротность, не менее: 45; Резонансная частота, не менее: 0.700 ГГц; Сопротивление обмотки постоянноми току, не более: 0.84 Ом; Допустимый ток обмотки: 500 мА; Диапазон рабочих температур: от -60 до +125 ℃; Упаковка: Катушка и лента; Типоразмер: 2520 (1008); Технология монтажа: SMT; Изготовитель: АО "НПО "ЭРКОН"
footprint КИК-2520-О (Катушка индуктивности с керамическим сердечником типоразмер 2520(1008))
pins: 1, 2

## КИК-2520-270 нГн ±2% O
designator L?, comment 270 нГн ±2%  (value not drawn)
Катушка индуктивности с керамическим сердечником и  финишным покрытием контактных площадок оловом; Номиналиная индуктивность: 270 нГн; Добротность, не менее: 45; Резонансная частота, не менее: 0.600 ГГц; Сопротивление обмотки постоянноми току, не более: 0.91 Ом; Допустимый ток обмотки: 500 мА; Диапазон рабочих температур: от -60 до +125 ℃; Упаковка: Катушка и лента; Типоразмер: 2520 (1008); Технология монтажа: SMT; Изготовитель: АО "НПО "ЭРКОН"
footprint КИК-2520-О (Катушка индуктивности с керамическим сердечником типоразмер 2520(1008))
pins: 1, 2

## КИК-2520-270 нГн ±5% O
designator L?, comment 270 нГн ±5%  (value not drawn)
Катушка индуктивности с керамическим сердечником и  финишным покрытием контактных площадок оловом; Номиналиная индуктивность: 270 нГн; Добротность, не менее: 45; Резонансная частота, не менее: 0.600 ГГц; Сопротивление обмотки постоянноми току, не более: 0.91 Ом; Допустимый ток обмотки: 500 мА; Диапазон рабочих температур: от -60 до +125 ℃; Упаковка: Катушка и лента; Типоразмер: 2520 (1008); Технология монтажа: SMT; Изготовитель: АО "НПО "ЭРКОН"
footprint КИК-2520-О (Катушка индуктивности с керамическим сердечником типоразмер 2520(1008))
pins: 1, 2

## КИК-2520-330 нГн ±2% O
designator L?, comment 330 нГн ±2%  (value not drawn)
Катушка индуктивности с керамическим сердечником и  финишным покрытием контактных площадок оловом; Номиналиная индуктивность: 330 нГн; Добротность, не менее: 45; Резонансная частота, не менее: 0.570 ГГц; Сопротивление обмотки постоянноми току, не более: 1.05 Ом; Допустимый ток обмотки: 450 мА; Диапазон рабочих температур: от -60 до +125 ℃; Упаковка: Катушка и лента; Типоразмер: 2520 (1008); Технология монтажа: SMT; Изготовитель: АО "НПО "ЭРКОН"
footprint КИК-2520-О (Катушка индуктивности с керамическим сердечником типоразмер 2520(1008))
pins: 1, 2

## КИК-2520-330 нГн ±5% O
designator L?, comment 330 нГн ±5%  (value not drawn)
Катушка индуктивности с керамическим сердечником и  финишным покрытием контактных площадок оловом; Номиналиная индуктивность: 330 нГн; Добротность, не менее: 45; Резонансная частота, не менее: 0.570 ГГц; Сопротивление обмотки постоянноми току, не более: 1.05 Ом; Допустимый ток обмотки: 450 мА; Диапазон рабочих температур: от -60 до +125 ℃; Упаковка: Катушка и лента; Типоразмер: 2520 (1008); Технология монтажа: SMT; Изготовитель: АО "НПО "ЭРКОН"
footprint КИК-2520-О (Катушка индуктивности с керамическим сердечником типоразмер 2520(1008))
pins: 1, 2

## КИК-2520-390 нГн ±2% O
designator L?, comment 390 нГн ±2%  (value not drawn)
Катушка индуктивности с керамическим сердечником и  финишным покрытием контактных площадок оловом; Номиналиная индуктивность: 390 нГн; Добротность, не менее: 45; Резонансная частота, не менее: 0.500 ГГц; Сопротивление обмотки постоянноми току, не более: 1.12 Ом; Допустимый ток обмотки: 470 мА; Диапазон рабочих температур: от -60 до +125 ℃; Упаковка: Катушка и лента; Типоразмер: 2520 (1008); Технология монтажа: SMT; Изготовитель: АО "НПО "ЭРКОН"
footprint КИК-2520-О (Катушка индуктивности с керамическим сердечником типоразмер 2520(1008))
pins: 1, 2

## КИК-2520-390 нГн ±5% O
designator L?, comment 390 нГн ±5%  (value not drawn)
Катушка индуктивности с керамическим сердечником и  финишным покрытием контактных площадок оловом; Номиналиная индуктивность: 390 нГн; Добротность, не менее: 45; Резонансная частота, не менее: 0.500 ГГц; Сопротивление обмотки постоянноми току, не более: 1.12 Ом; Допустимый ток обмотки: 470 мА; Диапазон рабочих температур: от -60 до +125 ℃; Упаковка: Катушка и лента; Типоразмер: 2520 (1008); Технология монтажа: SMT; Изготовитель: АО "НПО "ЭРКОН"
footprint КИК-2520-О (Катушка индуктивности с керамическим сердечником типоразмер 2520(1008))
pins: 1, 2

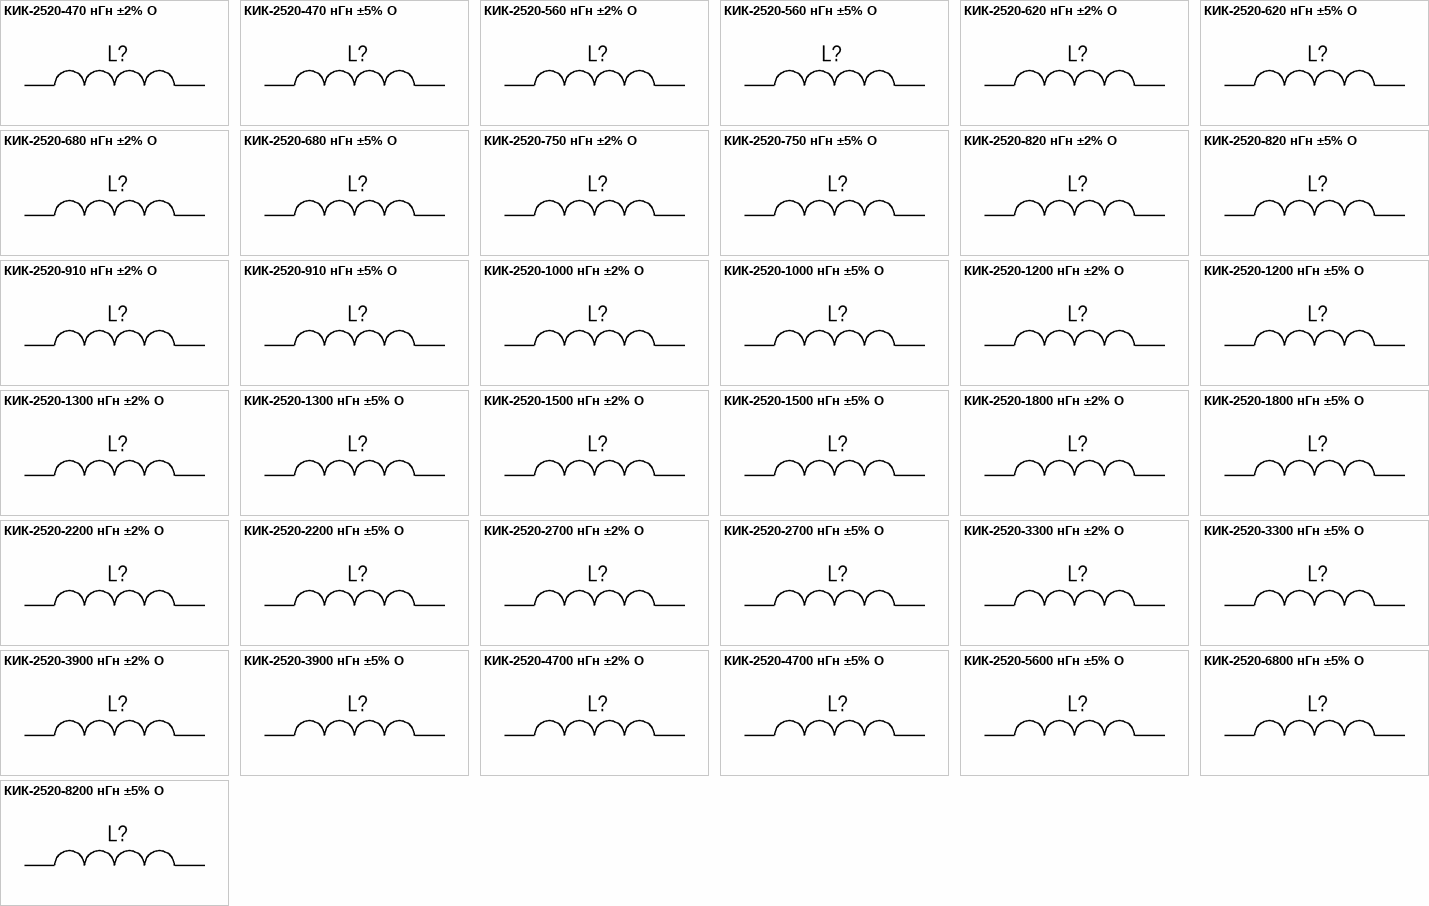
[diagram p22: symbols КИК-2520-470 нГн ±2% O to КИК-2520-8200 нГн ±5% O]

## КИК-2520-470 нГн ±2% O
designator L?, comment 470 нГн ±2%  (value not drawn)
Катушка индуктивности с керамическим сердечником и  финишным покрытием контактных площадок оловом; Номиналиная индуктивность: 470 нГн; Добротность, не менее: 45; Резонансная частота, не менее: 0.450 ГГц; Сопротивление обмотки постоянноми току, не более: 1.19 Ом; Допустимый ток обмотки: 470 мА; Диапазон рабочих температур: от -60 до +125 ℃; Упаковка: Катушка и лента; Типоразмер: 2520 (1008); Технология монтажа: SMT; Изготовитель: АО "НПО "ЭРКОН"
footprint КИК-2520-О (Катушка индуктивности с керамическим сердечником типоразмер 2520(1008))
pins: 1, 2

## КИК-2520-470 нГн ±5% O
designator L?, comment 470 нГн ±5%  (value not drawn)
Катушка индуктивности с керамическим сердечником и  финишным покрытием контактных площадок оловом; Номиналиная индуктивность: 470 нГн; Добротность, не менее: 45; Резонансная частота, не менее: 0.450 ГГц; Сопротивление обмотки постоянноми току, не более: 1.19 Ом; Допустимый ток обмотки: 470 мА; Диапазон рабочих температур: от -60 до +125 ℃; Упаковка: Катушка и лента; Типоразмер: 2520 (1008); Технология монтажа: SMT; Изготовитель: АО "НПО "ЭРКОН"
footprint КИК-2520-О (Катушка индуктивности с керамическим сердечником типоразмер 2520(1008))
pins: 1, 2

## КИК-2520-560 нГн ±2% O
designator L?, comment 560 нГн ±2%  (value not drawn)
Катушка индуктивности с керамическим сердечником и  финишным покрытием контактных площадок оловом; Номиналиная индуктивность: 560 нГн; Добротность, не менее: 45; Резонансная частота, не менее: 0.415 ГГц; Сопротивление обмотки постоянноми току, не более: 1.33 Ом; Допустимый ток обмотки: 400 мА; Диапазон рабочих температур: от -60 до +125 ℃; Упаковка: Катушка и лента; Типоразмер: 2520 (1008); Технология монтажа: SMT; Изготовитель: АО "НПО "ЭРКОН"
footprint КИК-2520-О (Катушка индуктивности с керамическим сердечником типоразмер 2520(1008))
pins: 1, 2

## КИК-2520-560 нГн ±5% O
designator L?, comment 560 нГн ±5%  (value not drawn)
Катушка индуктивности с керамическим сердечником и  финишным покрытием контактных площадок оловом; Номиналиная индуктивность: 560 нГн; Добротность, не менее: 45; Резонансная частота, не менее: 0.415 ГГц; Сопротивление обмотки постоянноми току, не более: 1.33 Ом; Допустимый ток обмотки: 400 мА; Диапазон рабочих температур: от -60 до +125 ℃; Упаковка: Катушка и лента; Типоразмер: 2520 (1008); Технология монтажа: SMT; Изготовитель: АО "НПО "ЭРКОН"
footprint КИК-2520-О (Катушка индуктивности с керамическим сердечником типоразмер 2520(1008))
pins: 1, 2

## КИК-2520-620 нГн ±2% O
designator L?, comment 620 нГн ±2%  (value not drawn)
Катушка индуктивности с керамическим сердечником и  финишным покрытием контактных площадок оловом; Номиналиная индуктивность: 620 нГн; Добротность, не менее: 45; Резонансная частота, не менее: 0.375 ГГц; Сопротивление обмотки постоянноми току, не более: 1.40 Ом; Допустимый ток обмотки: 300 мА; Диапазон рабочих температур: от -60 до +125 ℃; Упаковка: Катушка и лента; Типоразмер: 2520 (1008); Технология монтажа: SMT; Изготовитель: АО "НПО "ЭРКОН"
footprint КИК-2520-О (Катушка индуктивности с керамическим сердечником типоразмер 2520(1008))
pins: 1, 2

## КИК-2520-620 нГн ±5% O
designator L?, comment 620 нГн ±5%  (value not drawn)
Катушка индуктивности с керамическим сердечником и  финишным покрытием контактных площадок оловом; Номиналиная индуктивность: 620 нГн; Добротность, не менее: 45; Резонансная частота, не менее: 0.375 ГГц; Сопротивление обмотки постоянноми току, не более: 1.40 Ом; Допустимый ток обмотки: 300 мА; Диапазон рабочих температур: от -60 до +125 ℃; Упаковка: Катушка и лента; Типоразмер: 2520 (1008); Технология монтажа: SMT; Изготовитель: АО "НПО "ЭРКОН"
footprint КИК-2520-О (Катушка индуктивности с керамическим сердечником типоразмер 2520(1008))
pins: 1, 2

## КИК-2520-680 нГн ±2% O
designator L?, comment 680 нГн ±2%  (value not drawn)
Катушка индуктивности с керамическим сердечником и  финишным покрытием контактных площадок оловом; Номиналиная индуктивность: 680 нГн; Добротность, не менее: 45; Резонансная частота, не менее: 0.375 ГГц; Сопротивление обмотки постоянноми току, не более: 1.47 Ом; Допустимый ток обмотки: 400 мА; Диапазон рабочих температур: от -60 до +125 ℃; Упаковка: Катушка и лента; Типоразмер: 2520 (1008); Технология монтажа: SMT; Изготовитель: АО "НПО "ЭРКОН"
footprint КИК-2520-О (Катушка индуктивности с керамическим сердечником типоразмер 2520(1008))
pins: 1, 2

## КИК-2520-680 нГн ±5% O
designator L?, comment 680 нГн ±5%  (value not drawn)
Катушка индуктивности с керамическим сердечником и  финишным покрытием контактных площадок оловом; Номиналиная индуктивность: 680 нГн; Добротность, не менее: 45; Резонансная частота, не менее: 0.375 ГГц; Сопротивление обмотки постоянноми току, не более: 1.47 Ом; Допустимый ток обмотки: 400 мА; Диапазон рабочих температур: от -60 до +125 ℃; Упаковка: Катушка и лента; Типоразмер: 2520 (1008); Технология монтажа: SMT; Изготовитель: АО "НПО "ЭРКОН"
footprint КИК-2520-О (Катушка индуктивности с керамическим сердечником типоразмер 2520(1008))
pins: 1, 2

## КИК-2520-750 нГн ±2% O
designator L?, comment 750 нГн ±2%  (value not drawn)
Катушка индуктивности с керамическим сердечником и  финишным покрытием контактных площадок оловом; Номиналиная индуктивность: 750 нГн; Добротность, не менее: 45; Резонансная частота, не менее: 0.360 ГГц; Сопротивление обмотки постоянноми току, не более: 1.54 Ом; Допустимый ток обмотки: 360 мА; Диапазон рабочих температур: от -60 до +125 ℃; Упаковка: Катушка и лента; Типоразмер: 2520 (1008); Технология монтажа: SMT; Изготовитель: АО "НПО "ЭРКОН"
footprint КИК-2520-О (Катушка индуктивности с керамическим сердечником типоразмер 2520(1008))
pins: 1, 2

## КИК-2520-750 нГн ±5% O
designator L?, comment 750 нГн ±5%  (value not drawn)
Катушка индуктивности с керамическим сердечником и  финишным покрытием контактных площадок оловом; Номиналиная индуктивность: 750 нГн; Добротность, не менее: 45; Резонансная частота, не менее: 0.360 ГГц; Сопротивление обмотки постоянноми току, не более: 1.54 Ом; Допустимый ток обмотки: 360 мА; Диапазон рабочих температур: от -60 до +125 ℃; Упаковка: Катушка и лента; Типоразмер: 2520 (1008); Технология монтажа: SMT; Изготовитель: АО "НПО "ЭРКОН"
footprint КИК-2520-О (Катушка индуктивности с керамическим сердечником типоразмер 2520(1008))
pins: 1, 2

## КИК-2520-820 нГн ±2% O
designator L?, comment 820 нГн ±2%  (value not drawn)
Катушка индуктивности с керамическим сердечником и  финишным покрытием контактных площадок оловом; Номиналиная индуктивность: 820 нГн; Добротность, не менее: 45; Резонансная частота, не менее: 0.350 ГГц; Сопротивление обмотки постоянноми току, не более: 1.61 Ом; Допустимый ток обмотки: 400 мА; Диапазон рабочих температур: от -60 до +125 ℃; Упаковка: Катушка и лента; Типоразмер: 2520 (1008); Технология монтажа: SMT; Изготовитель: АО "НПО "ЭРКОН"
footprint КИК-2520-О (Катушка индуктивности с керамическим сердечником типоразмер 2520(1008))
pins: 1, 2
